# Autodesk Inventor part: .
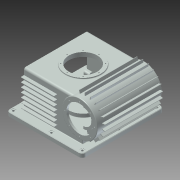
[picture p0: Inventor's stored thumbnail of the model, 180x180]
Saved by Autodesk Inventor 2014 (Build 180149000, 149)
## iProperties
Created: 2002-07
Part Number: .
Material: Ultem-1000
Description: gear-box.ipt.
Document SubType Name: Modeling
Density: 1.28 g/cm^3
Appearance: Zinc
ProtocolID: P00020801095336453
Protocol: P00020801095336453<@PID>[Version]<@EL>Version=2.2<@EL>[BaseView]<@EL>UpdateAll=0<@EL>EnableUpdate=<@EL>H2=582<@EL>W2=350<@EL>Top=55<@EL>Left=359<@EL>OnTop=0<@EL
Control State: 0
Master: False
Checked Out: False
Shininess: 52.0
Length Units: 11269
Angle Units: 11279
Time Units: 11290
Mass Units: 11283
Length Display Precision: 3
Angle Display Precision: 2
Density: 0.0
Volumn: 0.0
Area: 0.0
PropertySet Name: Model Information
Author: PaulN
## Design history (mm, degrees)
sketch "Sketch1"
  geometry: L1 (0, 0)-(330, 0); L2 (0, 210)-(0, 0); L3 (330, 0)-(330, 20.723); L4 (0, 210)-(274.411, 210); A1 r 100 centre (318, 120) between (330, 20.723) and (274.411, 210)
  constraints: 8 end point, 2 perpendicular, 2 point on circle, 1 centre point, 1 horizontal, 1 parallel, 1 other
  dimensions: "d0" = 210 distance of L2.start L1.start; "d1" = 330 distance of L1.start L1.end (= 2 x CenDist); "d2" = 200 diameter of A1; "d4" = 120 distance from line of L1 A1.centre; "d17" = 12 distance from line of L3 A1.centre
extrude "Extrusion1" new body sketch "Sketch1" distance "d5" = 363 (= 2.2 x CenDist); taper "d6" = 0 deg
sketch "Sketch2"
  geometry: C1 r 82.5 at (318, 120); 3 further points
  constraints: 1 centre point, 2 other
  dimensions: "d8" = 165 diameter of C1
extrude "Extrusion2" join sketch "Sketch2" distance "d9" = 3.175; taper "d10" = 0 deg
workaxis "Work Axis1"
shell "Shell2" dims "d26" = 8
sketch "Sketch4"
  geometry: L1 (318, 72.6)-(318, -435.6) reference; L2 (274.411, 0)-(0, 0) reference; C1 r 100 at (153, -181.5)
  constraints: 1 centre point
  dimensions: "d20" = 200 diameter of C1; "CenDist" = 165 distance from line of C1.centre L1; "d23" = 181.5 distance from line of C1.centre L2 (derived)
extrude "Extrusion4" join sketch "Sketch4" distance "d24" = 6; taper "d25" = 0 deg
workplane "Work Plane2"
sketch "Sketch9"
  geometry: C1 r 70 at (153, 173.5); C2 r 82 at (153, 173.5); 1 further point
  constraints: 2 centre point, 2 coincident
  dimensions: "DIAM_OUT" = 140 diameter of C1; "d249" = 12 radial gap between concentric circles of C2 C1
extrude "Extrusion8" join sketch "Sketch9" distance "d51" = 20; taper "d52" = 0 deg
sketch "Sketch12"
  geometry: C1 r 100 at (0, 0) reference; C2 r 80 at (0, 0)
  constraints: 1 centre point, 1 coincident
  dimensions: "d61" = 20 radial gap between concentric circles of C1 C2
extrude "Extrusion11" cut sketch "Sketch12" stored distance "d62" = 2.54; taper "d63" = 0 deg
fillet "Fillet3" dims "d64" = 3 (derived)
sketch "Sketch13"
  geometry: C1 r 80 at (153, -173.5) reference; C2 r 83 at (153, -173.5); C3 r 95 at (153, -173.5)
  constraints: 2 centre point, 2 coincident
  dimensions: "d65" = 3 radial gap between concentric circles of C1 C2; "d66" = 12 radial gap between concentric circles of C3 C2
extrude "Extrusion12" join sketch "Sketch13" distance "d67" = 12; taper "d68" = 0 deg
sketch "Sketch14"
  geometry: L1 (330, 363)-(0, 363) reference; L2 (0, 0)-(0, 363) reference; L3 (0, 0)-(330, 0) reference; L4 (330, 0)-(330, 363) reference; L5 (-50, 413)-(380, 413); L6 (380, 413)-(380, -50); L7 (380, -50)-(-50, -50); L8 (-50, -50)-(-50, 413)
  constraints: 8 end point, 3 other
  dimensions: "d70" = 50 distance between parallel lines of L5 L1
extrude "Extrusion13" join sketch "Sketch14" distance "d71" = 25; taper "d72" = 0 deg
sketch "Sketch16"
  geometry: L1 (-400.5, 363)-(-418, 363); L2 (-418, 0)-(-418, 363) reference; L3 (-400.5, 363)-(-400.5, 366.175) reference; L4 (-400.5, 366.175)-(-414.825, 366.175); L5 (-318, -73.367)-(-318, 440.199) reference; A1 r 3.175 centre (-414.825, 363) between (-414.825, 366.175) and (-418, 363)
  constraints: 4 end point, 2 point on circle, 2 tangent, 1 centre point, 1 horizontal, 1 perpendicular
revolve "Revolution2" sketch "Sketch16" stored, may be unused: angle "d75" = 90 deg
sketch "Sketch19"
  geometry: L1 (380, 413)-(380, -50) reference; L2 (-50, 413)-(380, 413) reference; L3 (-50, -50)-(-50, 413) reference; L4 (380, -50)-(-50, -50) reference; L5 (-10, 2)-(-10, 361); L6 (2, 373)-(328, 373); L7 (340, 361)-(340, 2); L8 (328, -10)-(2, -10); A1 r 12 centre (2, 2) between (-10, 2) and (2, -10); A2 r 12 centre (2, 361) between (2, 373) and (-10, 361); A3 r 12 centre (328, 361) between (340, 361) and (328, 373); A4 r 12 centre (328, 2) between (328, -10) and (340, 2)
  constraints: 8 end point, 8 point on circle, 8 tangent, 4 centre point, 3 equal radius, 3 other
  dimensions: "d89" = 40 distance between parallel lines of L4 L8; "d90" = 12 radius of A1
extrude "Extrusion15" cut sketch "Sketch19" distance "d91" = 10; taper "d92" = 0 deg
fillet "Fillet5" dims "d76" = 20
chamfer "Chamfer2" distance "d77" = 2.5; stored, may be unused: second distance "d78" = 2.5, angle "d352" = 45 deg
fillet "Fillet9" dims "d84" = 12, "d85" = 3, "d86" = 3
sketch "Sketch22"
  geometry: A1 r 20 centre (360, 30) between (380, 30) and (360, 50) reference; A2 r 20 centre (-30, 30) between (-30, 50) and (-50, 30) reference; A3 r 20 centre (-30, -393) between (-50, -393) and (-30, -413) reference; A4 r 20 centre (360, -393) between (360, -413) and (380, -393) reference; 4 further points
  constraints: 3 horizontal alignment, 3 vertical alignment
  dimensions: "d114" = 215 distance of A2.centre point (185, 30) (derived); "d115" = 215.5 distance of point (-30, -185.5) A2.centre (derived)
hole "Hole3" sketch "Sketch22" at (185, -393), (360, -185.5), (-30, -185.5), (185, 30), (-30, -393), (-30, 30), (360, -393), (360, 30) diameter "d116" = 12; stored, may be unused: countersink angle "d120" = 82 deg, drill point angle "d122" = 118 deg; dims "d117" = 12.7, "d118" = 25, "d119" = 1.25, "d121" = 19.05
sketch "Sketch46"
  geometry: L1 (8, 5)-(8, 199) reference; L2 (8, 199)-(355, 199) reference; L3 (355, 199)-(355, 5) reference; L4 (355, 5)-(8, 5) reference; L5 (5, 8)-(5, 196); L6 (11, 202)-(352, 202); L7 (358, 196)-(358, 8); L8 (352, 2)-(11, 2); A1 r 6 centre (352, 196) between (358, 196) and (352, 202); A2 r 6 centre (352, 8) between (352, 2) and (358, 8); A3 r 6 centre (11, 8) between (5, 8) and (11, 2); A4 r 6 centre (11, 196) between (11, 202) and (5, 196)
  constraints: 8 end point, 8 point on circle, 8 tangent, 4 centre point, 3 equal radius, 3 other
  dimensions: "d338" = 3 distance between parallel lines of L7 L3; "d339" = 6 radius of A1
extrude "Extrusion28" cut sketch "Sketch46" distance "d340" = 2; taper "d341" = 0 deg
sketch "Sketch47"
  geometry: L1 (8, 5)-(355, 5) reference; L2 (8, 199)-(8, 5) reference; L3 (355, 199)-(8, 199) reference; L4 (355, 5)-(355, 199) reference; L5 (358, 8)-(358, 196) reference; L6 (8, 179)-(18, 179); L7 (28, 189)-(28, 199); L8 (28, 5)-(28, 15); L9 (18, 25)-(8, 25); L10 (335, 5)-(335, 15); L11 (345, 25)-(355, 25); L12 (335, 199)-(335, 189); L13 (345, 179)-(355, 179); C1 r 4.5 at (18, 189); C2 r 4.5 at (18, 15); C3 r 4.5 at (345, 15); C4 r 4.5 at (345, 189); A1 r 10 centre (345, 189) between (335, 189) and (345, 179); A2 r 10 centre (345, 15) between (345, 25) and (335, 15); A3 r 10 centre (18, 15) between (28, 15) and (18, 25); A4 r 10 centre (18, 189) between (18, 179) and (28, 189)
  constraints: 16 end point, 8 centre point, 8 point on circle, 8 point on line, 8 tangent, 7 perpendicular, 5 collinear, 4 coincident, 3 equal length, 3 equal radius
  dimensions: "d342" = 10 radius of A1; "d343" = 20 distance between parallel lines of L2 L7; "d344" = 9 diameter of C1; "d349" = 9 diameter of C4; "d350" = 9 diameter of C3; "d351" = 9 diameter of C2
extrude "Extrusion29" join sketch "Sketch47" distance "d345" = 30; taper "d346" = 0 deg
workplane "Work Plane11"
workplane "Work Plane12"
sketch "Sketch24"
  geometry: L1 (363, 0)-(363, 195) reference; L2 (320.675, 4.445)-(14.605, 4.445) reference; L3 (363, 19)-(381, 19); L4 (381, 19)-(381, 19.277); L5 (380.028, 20.292)-(363, 21.036); L6 (380.028, 17.708)-(363, 16.964); L7 (381, 19)-(381, 18.723); L8 (363, 16.964)-(363, 21.036); A1 r 1.016 centre (379.984, 19.277) between (381, 19.277) and (380.028, 20.292); A2 r 1.016 centre (379.984, 18.723) between (380.028, 17.708) and (381, 18.723); 2 further points
  constraints: 12 end point, 6 point on line, 4 point on circle, 4 tangent, 2 centre point, 2 symmetric about line, 1 collinear, 1 equal radius, 1 parallel, 1 perpendicular, 2 other
  dimensions: "d134" = 5 deg angle of L6 L5; "d135" = 2.5 distance of point (381, 17.75) point (381, 20.25); "d136" = 18 distance between parallel lines of L4 L8; "d139" = 1.016 radius of A1; "d150" = 19 distance from line of L1.start L3
extrude "Cooler Left Side" join sketch "Sketch24" stored distance "d137" = 165 (derived); taper "d138" = 0 deg
pattern_linear "Pattern Cooler Left" dims "d142" = 25
sketch "Sketch25"
  geometry: L1 (0, 195)-(0, 0) reference; L2 (0, 19)-(-18, 19); L3 (-18, 19)-(-18, 18.723); L4 (-17.028, 17.708)-(0, 16.964); L5 (-18, 19)-(-18, 19.277); L6 (-17.028, 20.292)-(0, 21.036); L7 (0, 21.036)-(0, 16.964); A1 r 1.016 centre (-16.984, 18.723) between (-18, 18.723) and (-17.028, 17.708); A2 r 1.016 centre (-16.984, 19.277) between (-17.028, 20.292) and (-18, 19.277); 2 further points
  constraints: 12 end point, 6 point on line, 4 point on circle, 4 tangent, 2 centre point, 2 symmetric about line, 1 collinear, 1 equal radius, 1 perpendicular, 2 other
  dimensions: "d143" = 5 deg angle of L4 L6; "d144" = 18 distance between parallel lines of L7 L5; "d145" = 2.5 distance of point (-18, 17.75) point (-18, 20.25); "d146" = 19 distance from line of L1.end L2 (derived); "d147" = 1.016 radius of A1
extrude "Cooler Right Side" join sketch "Sketch25" distance "d148" = 305 (derived); taper "d149" = 0 deg
pattern_linear "Pattern Cooler Right" dims "d153" = 25
workplane "Work Plane3"
sketch "Sketch30"
  geometry: L1 (292.118, 216.593)-(287.718, 233.013); L2 (318, 120)-(318, 229.875); L3 (287.718, 233.013)-(287.45, 232.942); L4 (286.721, 231.74)-(290.198, 216.058); L5 (289.218, 232.409)-(294.048, 217.089); L6 (287.718, 233.013)-(287.986, 233.085); L7 (290.198, 216.058)-(294.048, 217.089); A1 r 100 centre (318, 120) between (329.947, 20.716) and (266.865, 205.937) reference; A2 r 1.016 centre (287.713, 231.96) between (287.45, 232.942) and (286.721, 231.74); A3 r 1.016 centre (288.249, 232.104) between (289.218, 232.409) and (287.986, 233.085); 2 further points
  constraints: 14 end point, 6 point on circle, 5 point on line, 4 tangent, 2 centre point, 2 symmetric about line, 1 equal radius, 1 parallel, 1 perpendicular, 1 vertical, 2 other
  dimensions: "d170" = 17 distance of L1.start L1.end; "d171" = 15 deg angle of L2 L1; "d172" = 2.5 distance of point (288.926, 233.337) point (286.511, 232.69); "d173" = 5 deg angle of L5 L4; "d174" = 1.016 radius of A2
extrude "Cooler Circular" join sketch "Sketch30" distance "d175" = 328 (derived); taper "d176" = 0 deg
pattern_circular "Pattern Cooler Cicular" dims angle "d179" = 180 deg
sketch "Sketch32"
  geometry: C1 r 100 at (0, 0); C2 r 80 at (0, 0) reference; C3 r 100 at (0, 0) reference; 3 further points
  constraints: 2 horizontal alignment, 1 centre point, 1 coincident, 2 other
  dimensions: "d348" = 10 dimension on C1
hole "Hole5" sketch "Sketch32" at (-90, 0) diameter "d184" = 6; stored, may be unused: countersink angle "d188" = 82 deg, drill point angle "d190" = 118 deg; dims "d185" = 12.7, "d186" = 9.525, "d187" = 6.35, "d189" = 19.05
pattern_circular "Circular Pattern5" dims angle "d193" = 360 deg
workplane "Work Plane10"
sketch "Holders Sketch"
  geometry: L1 (-92, 8)-(-92, 355) reference; L2 (-46, 345.2)-(-60, 345.2); L3 (-60, 345.2)-(-60, 326.35); L4 (-60, 326.35)-(-92, 326.35); L5 (-92, 326.35)-(-92, 316.35); L6 (-92, 316.35)-(-60, 316.35); L7 (-60, 316.35)-(-60, 297.5); L8 (-60, 297.5)-(-46, 297.5); L9 (-92, 36.5)-(-92, 46.5); L10 (-92, 46.5)-(-47.5, 46.5); L11 (-47.5, 46.5)-(-47.5, 51.5); L12 (-47.5, 51.5)-(-37.5, 51.5); L13 (-37.5, 51.5)-(-37.5, 35.5); L14 (-33.5, 31.5)-(-47.5, 31.5); L15 (-47.5, 31.5)-(-47.5, 36.5); L16 (-47.5, 36.5)-(-92, 36.5); L17 (0, -72.6)-(0, 435.6) reference; L18 (-50, 341.2)-(-50, 301.5); L19 (41.713, 8)-(-92, 8) reference; L20 (-50, 341.2)-(-46, 341.2); L21 (-46, 341.2)-(-46, 345.2); L22 (-50, 301.5)-(-46, 301.5); L23 (-46, 301.5)-(-46, 297.5); L24 (-74.5, 355)-(74.5, 355) reference; L25 (-37.5, 35.5)-(-33.5, 35.5); L26 (-33.5, 35.5)-(-33.5, 31.5); 4 further points
  constraints: 44 end point, 9 parallel, 8 perpendicular, 7 collinear, 3 midpoint, 2 point on line
  dimensions: "d256" = 10 distance between parallel lines of L6 L4; "d257" = 10 distance between parallel lines of L16 L10; "d258" = 10 distance between parallel lines of L11 L13; "D_in2" = 75 diameter of L13 L17; "d281" = 10 distance between parallel lines of L7 L18; "D_in1" = 100 diameter of L18 L17; "B_in1" = 39.7 distance of L18.start L18.end; "d294" = 4 distance of L18.start L20.end; "d295" = 4 distance of L20.end L2.start; "L_shaft_2" = 130 distance from line of point (-92, 181.5) L12; "L_shaft_1" = 120 distance from line of point (-92, 181.5) L22; "d303" = 4 distance of L25.end L14.start; "d304" = 4 distance between parallel lines of L26 L13; "B_in2" = 16 distance of L12.end L13.end
revolve "Holders" sketch "Holders Sketch" stored, may be unused: angle "d268" = 180 deg
sketch "Sketch39"
  geometry: L1 (0, 32)-(0, 0) reference; L2 (4, 0.087)-(0, 32); A1 r 92 centre (0, 92) between (0, 0) and (4, 0.087) reference
  constraints: 2 end point
extrude "Holder Cut" cut sketch "Sketch39" stored distance "d269" = 10; taper "d270" = 0 deg
fillet "Fillet11" dims "d194" = 3
fillet "Fillet21" dims "d273" = 4
fillet "Fillet22" dims "d274" = 3
fillet "Fillet12" dims "d220" = 4
fillet "Fillet14" dims "d232" = 2
sketch "Sketch23"
  geometry: C1 r 96.825 at (0, 0) reference; C2 r 74.5 at (0, 0) reference; 2 further points
  constraints: 2 horizontal alignment, 1 coincident, 2 other
  dimensions: "d123" = 10 dimension on C2
hole "Hole7" sketch "Sketch23" at (84.5, 0) diameter "d222" = 6; stored, may be unused: countersink angle "d226" = 82 deg, drill point angle "d228" = 118 deg; dims "d223" = 12.7, "d224" = 9.525, "d225" = 6.35, "d227" = 25
pattern_circular "Circular Pattern6" dims angle "d231" = 360 deg
sketch "Sketch41"
  geometry: L1 (20, 4)-(4, 4) reference; L2 (20, 14)-(20, 4) reference; L3 (20, -71)-(4, -71) reference; 2 further points
  constraints: 1 vertical alignment
  dimensions: "d306" = 5 distance from line of L1 point (8, 9); "d307" = 12 distance from line of L2 point (8, 9); "d308" = 5 distance from line of L3 point (8, -76)
hole "Hole8" sketch "Sketch41" at (8, 9), (8, -76) diameter "d309" = 5; stored, may be unused: countersink angle "d313" = 82 deg, drill point angle "d315" = 118 deg; dims "d310" = 6, "d311" = 4, "d312" = 2, "d314" = 10
sketch "Sketch42"
  geometry: L1 (0, 14)-(0, 0) reference; L2 (-47.7, 14)-(-28.85, 14) reference; L3 (-47.7, 0)-(-47.7, 14) reference; L4 (-47.7, -106)-(-28.85, -106) reference; 4 further points
  constraints: 2 horizontal alignment, 2 vertical alignment
  dimensions: "d316" = 10 distance from line of L3 point (-37.7, 9); "d317" = 10 distance from line of L1 point (-10, 9); "d318" = 5 distance from line of L2 point (-37.7, 9); "d319" = 5 distance from line of L4 point (-37.7, -101)
hole "Hole9" sketch "Sketch42" at (-37.7, 9), (-10, 9), (-37.7, -101), (-10, -101) diameter "d320" = 5; stored, may be unused: countersink angle "d324" = 82 deg, drill point angle "d326" = 118 deg; dims "d321" = 6, "d322" = 4, "d323" = 2, "d325" = 10
body "Solid1"
other parameters: "d169" = -25, "d255" = 90 deg, "d275" = 90 deg
